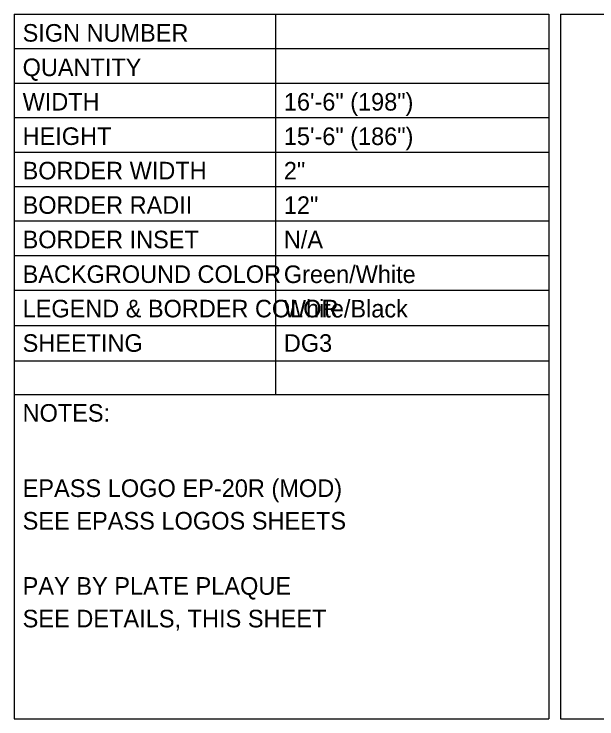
# Model space of a CAD drawing. Extents: x 10268312 to 10268706, y 2142548 to 2142786.
# Drawn here: x 10268318.48 to 10268343.28, y 2142657.53 to 2142687.53 of the extents above; entities that cross this region are included whole.
import ezdxf

# ---------------------------------------------------------------- set-up
doc = ezdxf.new("R2010")
doc.units = 0
doc.layers.add('SumBoxLines_dp', color=7, linetype='Continuous')
doc.layers.add('TextMisc', color=7, linetype='Continuous')

msp = doc.modelspace()

# ---------------------------------------------------------------- linework, layer by layer
at = {"layer": 'SumBoxLines_dp'}
for p, q in [((10268318.48, 2142687.532), (10268318.48, 2142657.532)), ((10268318.48, 2142687.532), (10268341.23, 2142687.532)), ((10268329.598, 2142687.528), (10268329.598, 2142671.345)), ((10268341.23, 2142687.532), (10268341.23, 2142657.532)), ((10268341.73, 2142687.532), (10268341.73, 2142657.532)), ((10268341.73, 2142687.532), (10268393.98, 2142687.532)), ((10268318.48, 2142686.066), (10268341.23, 2142686.066)), ((10268318.48, 2142684.59), (10268341.23, 2142684.59)), ((10268318.48, 2142683.125), (10268341.23, 2142683.125)), ((10268318.48, 2142681.659), (10268341.23, 2142681.659)), ((10268318.48, 2142680.193), (10268341.23, 2142680.193)), ((10268318.48, 2142678.727), (10268341.23, 2142678.727)), ((10268318.48, 2142677.261), (10268341.23, 2142677.261)), ((10268318.48, 2142675.786), (10268341.23, 2142675.786)), ((10268318.48, 2142674.281), (10268341.23, 2142674.281)), ((10268318.48, 2142672.776), (10268341.23, 2142672.776)), ((10268318.478, 2142671.345), (10268341.229, 2142671.345)), ((10268318.48, 2142657.532), (10268341.23, 2142657.532)), ((10268341.73, 2142657.532), (10268393.98, 2142657.532))]:
    msp.add_line(p, q, dxfattribs=at)

# ---------------------------------------------------------------- texts
at = {"layer": 'TextMisc'}
for s, height, p in [('SIGN NUMBER', 0.74756, (10268318.841, 2142686.359)), ('QUANTITY', 0.7476, (10268318.841, 2142684.893)), ('WIDTH', 0.7476, (10268318.841, 2142683.427)), ('16\'-6" (198")', 0.74756, (10268329.959, 2142683.424)), ('HEIGHT', 0.7476, (10268318.841, 2142681.962)), ('15\'-6" (186")', 0.74756, (10268329.959, 2142681.958)), ('BORDER WIDTH', 0.74756, (10268318.841, 2142680.496)), ('2"', 0.7476, (10268329.959, 2142680.492)), ('BORDER RADII', 0.74756, (10268318.841, 2142679.03)), ('12"', 0.7476, (10268329.959, 2142679.026)), ('BORDER INSET', 0.74756, (10268318.841, 2142677.564)), ('N/A', 0.7476, (10268329.959, 2142677.561)), ('BACKGROUND COLOR', 0.74756, (10268318.841, 2142676.089)), ('Green/White', 0.74756, (10268329.959, 2142676.085)), ('White/Black', 0.74756, (10268329.959, 2142674.619)), ('LEGEND & BORDER COLOR', 0.74756, (10268318.841, 2142674.623)), ('SHEETING', 0.7476, (10268318.841, 2142673.157)), ('DG3', 0.7476, (10268329.959, 2142673.157)), ('NOTES:', 0.7476, (10268318.84, 2142670.184)), ('EPASS LOGO EP-20R (MOD)', 0.75, (10268318.84, 2142666.977)), ('SEE EPASS LOGOS SHEETS', 0.75, (10268318.84, 2142665.59)), ('PAY BY PLATE PLAQUE', 0.75, (10268318.84, 2142662.815)), ('SEE DETAILS, THIS SHEET', 0.75, (10268318.84, 2142661.427))]:
    msp.add_text(s, height=height, dxfattribs=at).set_placement(p)

doc.saveas('drawing.dxf')
